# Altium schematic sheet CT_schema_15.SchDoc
size 147 x 119 mm
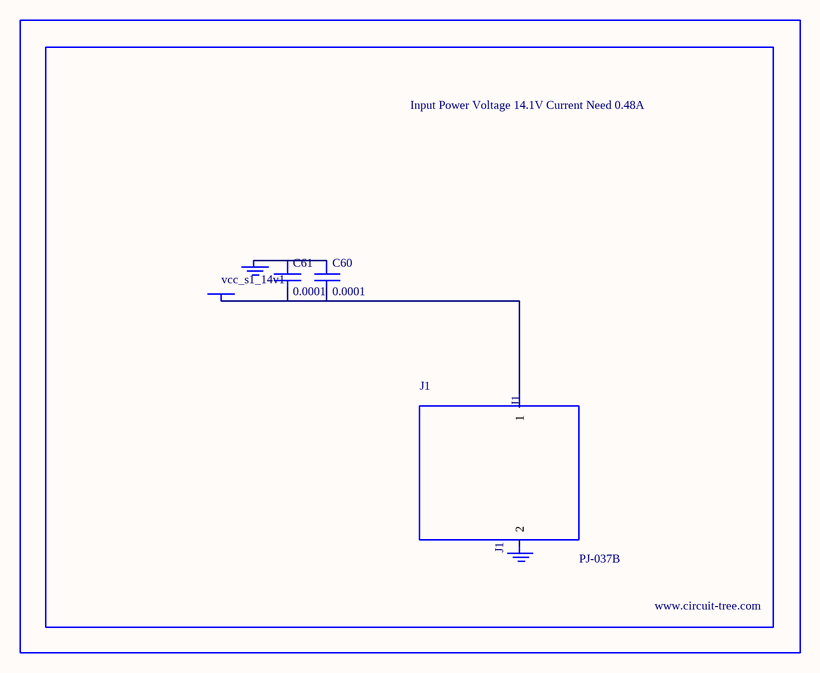
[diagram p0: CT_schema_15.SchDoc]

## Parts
BORDER14  (no value)
C60  0.0001  [EXV-9H]
C61  0.0001  [EXV-9H]
GND_INSTANCE_14_0  (no value)
GND_INSTANCE_14_1  (no value)
J1  PJ-037B  [PJ-037B_PACKAGE]
POWER_INSTANCE_14_0  vcc_s1_14v1

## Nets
NetC60_1: C60.1 C61.1 GND_INSTANCE_14_0.0(GND)
NetC60_2: C60.2 C61.2 J1.1 POWER_INSTANCE_14_0.0(PWR)

Not connected (* = marked no-connect by the designer): GND_INSTANCE_14_1 0(GND); J1 2

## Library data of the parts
BORDER14 = BORDER_PAGE14
C60 C61 = EDK107M035A9HAA
GND_INSTANCE_14_0 GND_INSTANCE_14_1 = GND
POWER_INSTANCE_14_0 = PWR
